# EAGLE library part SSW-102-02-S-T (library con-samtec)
THROUGH-HOLE .025" SQ POST SOCKET Source: Samtec SSW.pdf
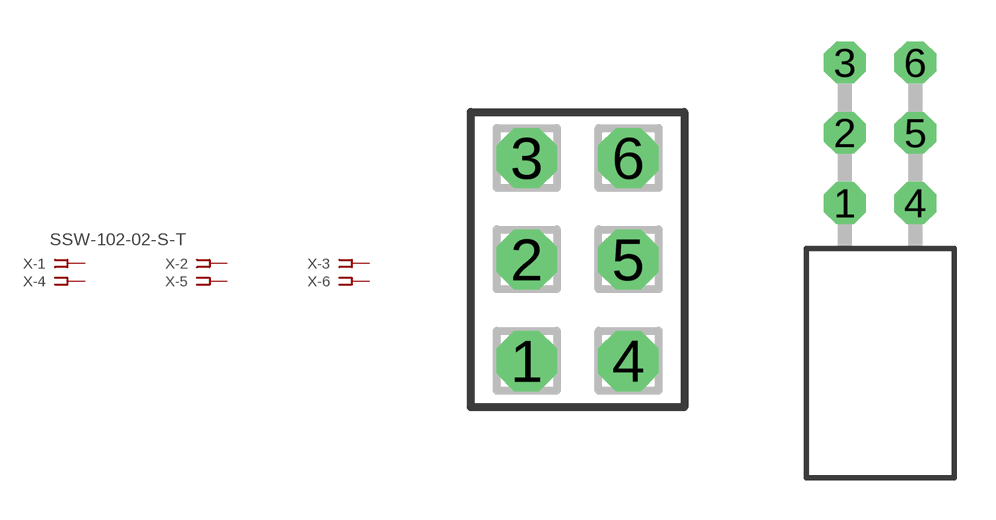
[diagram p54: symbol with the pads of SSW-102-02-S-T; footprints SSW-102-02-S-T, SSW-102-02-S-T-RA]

Designator prefix X; gates -1=FPINV -2=FPIN -3=FPIN -4=FPIN -5=FPIN -6=FPIN

## SSW-102-02-S-T (OC_FARNELL: unknown; OC_NEWARK: unknown)  [SSW-102-02-S-T]
1  -1:1  pas
2  -2:1  pas
3  -3:1  pas
4  -4:1  pas
5  -5:1  pas
6  -6:1  pas

## SSW-102-02-S-TRA (MPN: SSW-102-02-S-T-RA; OC_FARNELL: unknown; OC_NEWARK: 82P1708)  [SSW-102-02-S-T-RA]
Pads as for SSW-102-02-S-T

## Footprint SSW-102-02-S-T (pad centres in mm)
THROUGH-HOLE .025" SQ POST SOCKET Source: Samtec SSW.pdf
drill 1 pad 1.5 octagon: 1 -1.27,-2.54; 2 -1.27,0; 3 -1.27,2.54; 4 1.27,-2.54; 5 1.27,0; 6 1.27,2.54

## Footprint SSW-102-02-S-T-RA (pad centres in mm)
THROUGH-HOLE .025" SQ POST SOCKET Source: Samtec SSW.pdf
drill 1 pad 1.5 octagon: 1 -1.27,1.524; 2 -1.27,4.064; 3 -1.27,6.604; 4 1.27,1.524; 5 1.27,4.064; 6 1.27,6.604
